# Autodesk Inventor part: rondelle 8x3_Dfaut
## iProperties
Created: 2006-03
Part Number: rondelle 8x3_Dfaut
Document SubType Name: Modeling
Designer: Flavien MARTY
Author: Flavien MARTY
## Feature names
1. Base1
